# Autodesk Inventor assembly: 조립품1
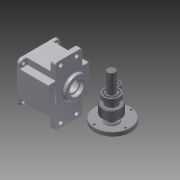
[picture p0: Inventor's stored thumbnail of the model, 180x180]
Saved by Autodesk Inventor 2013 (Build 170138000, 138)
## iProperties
Created: 2015-07
Part Number: 조립품1
Document SubType Name: Assembly
Designer: user
Author: user
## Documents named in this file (9)
- C:\Users\user\Desktop\450734V1028\조립품1.iam
- C:\Users\user\Desktop\450734V1028\메인축.ipt
- C:\Users\user\Desktop\450734V1028\서브축.ipt
- C:\Users\user\Desktop\450734V1028\베어링 608.ipt
- 베어링 608.ipt
- C:\Users\user\Desktop\450734V1028\베어링 6003.ipt
- 베어링 6003.ipt
- C:\Users\user\Desktop\450734V1028\커버.ipt
- C:\Users\user\Desktop\450734V1028\본체.ipt
